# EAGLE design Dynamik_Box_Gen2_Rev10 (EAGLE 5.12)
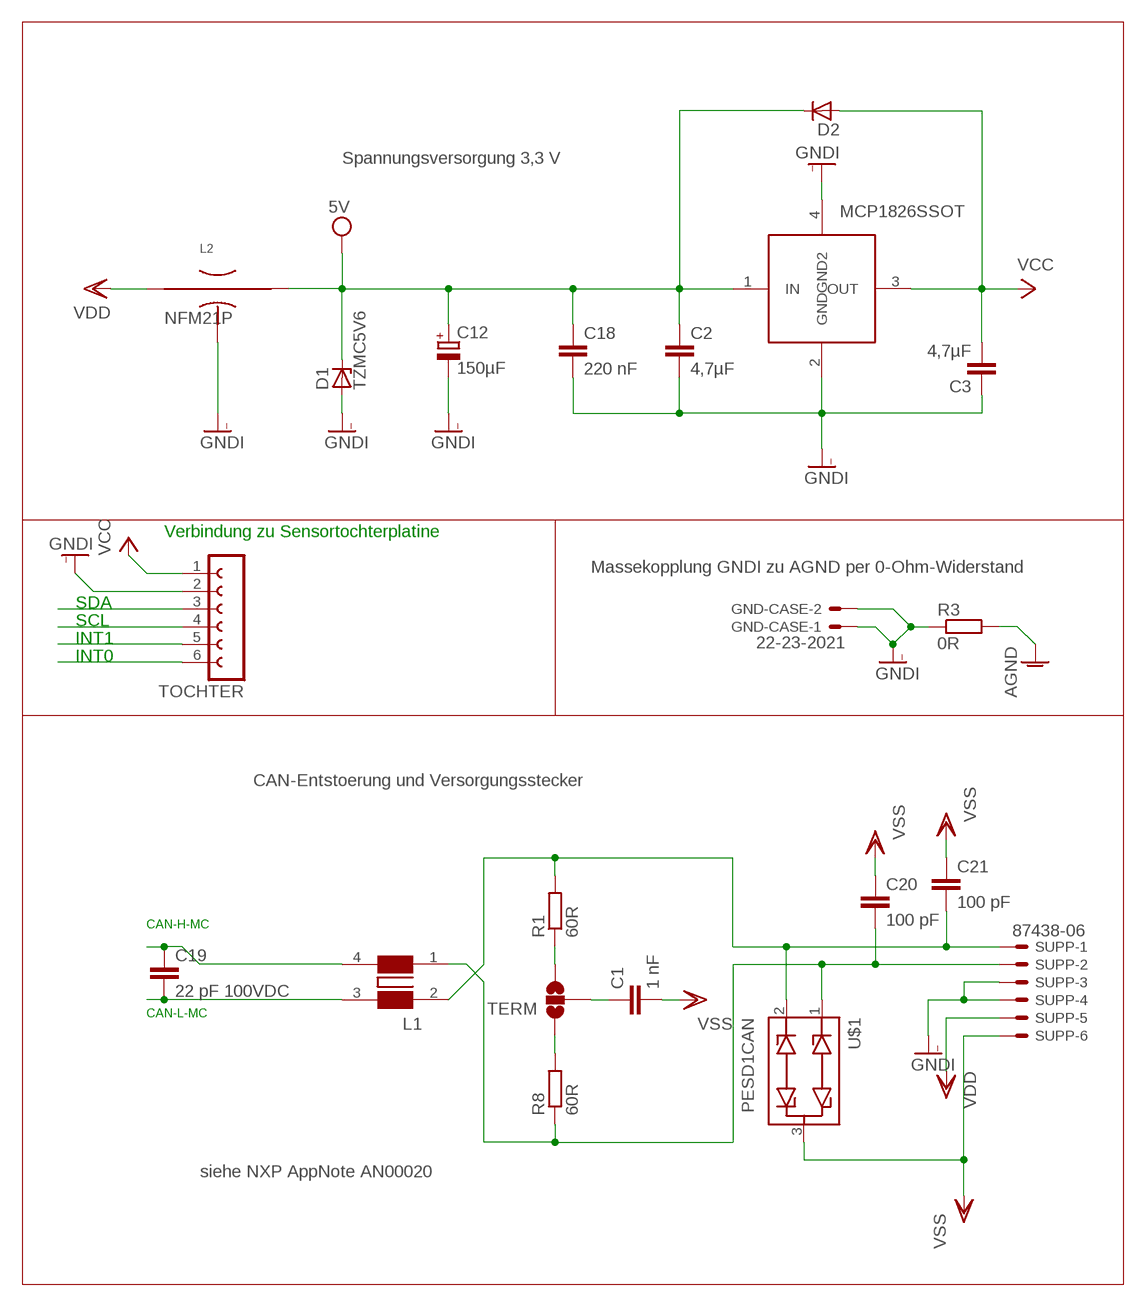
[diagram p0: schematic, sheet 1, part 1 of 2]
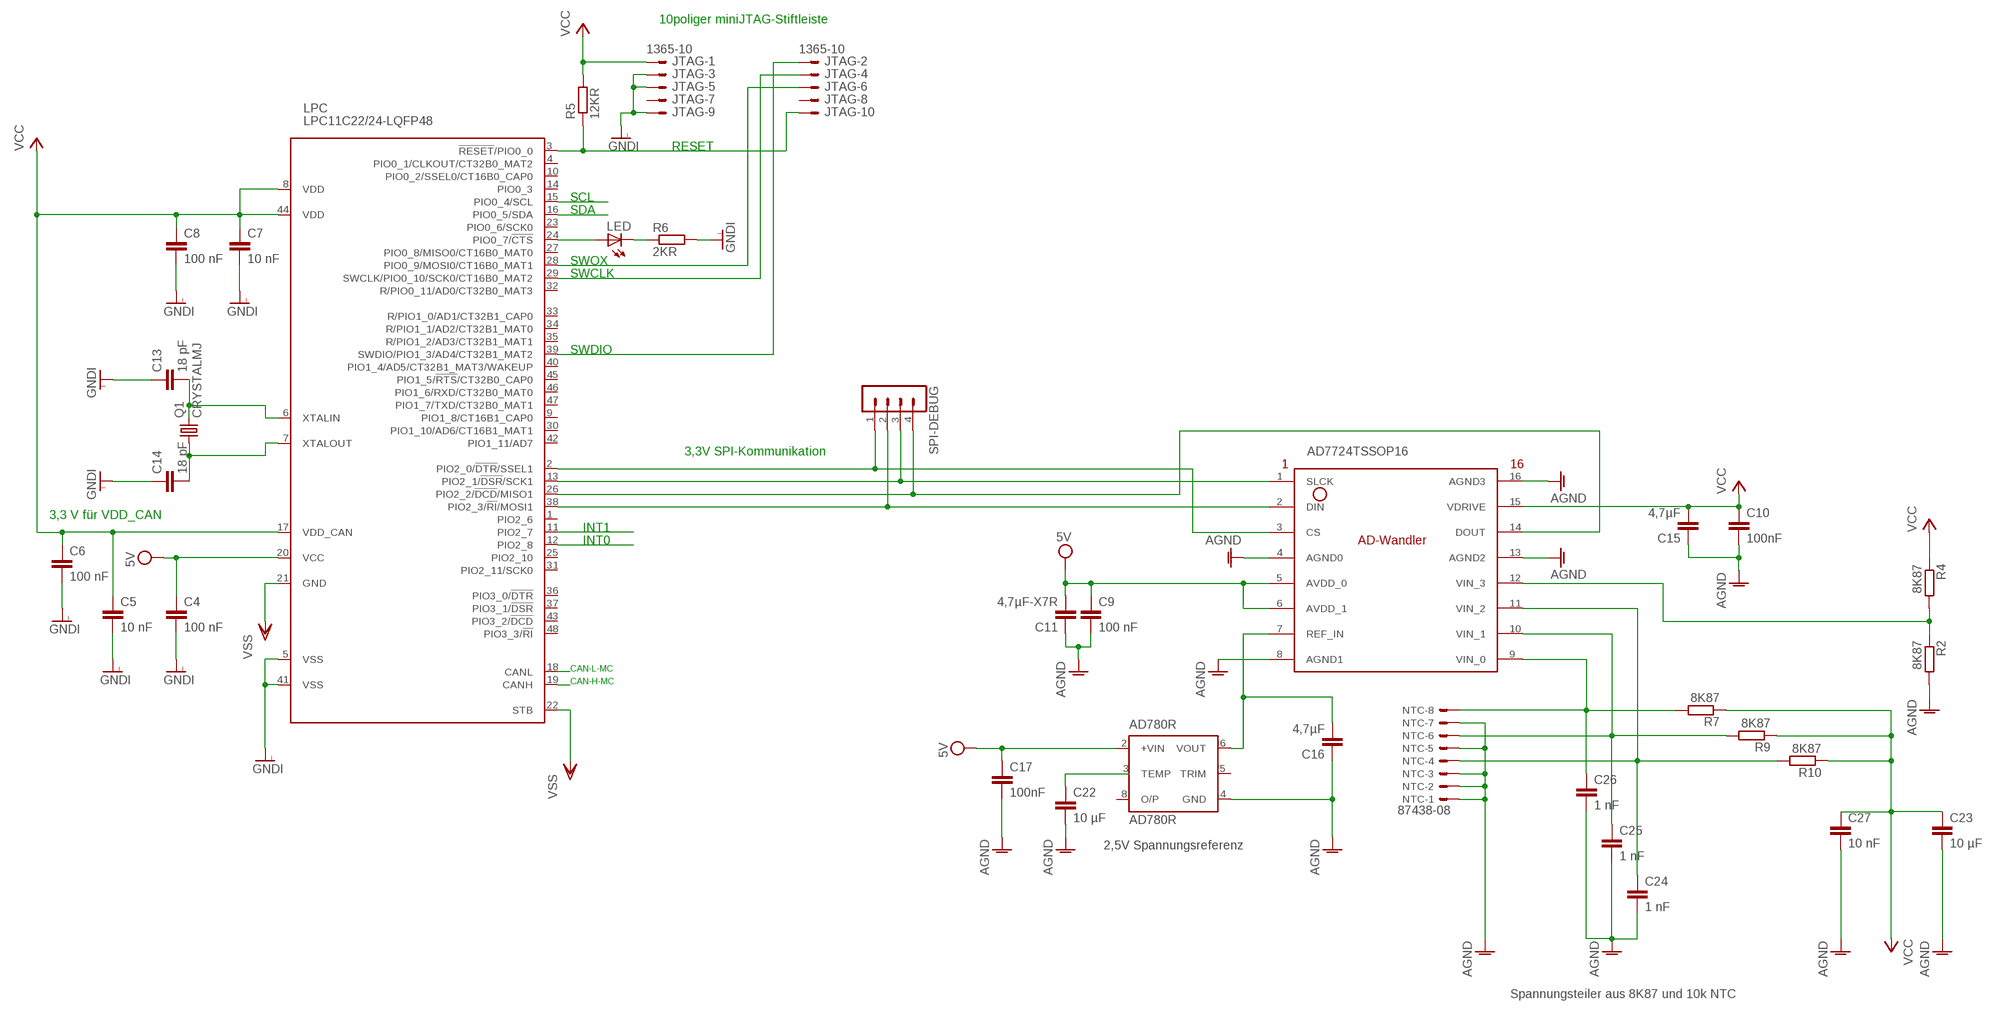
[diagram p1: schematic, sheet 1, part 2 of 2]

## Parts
AD780R  AD780R  [SO8]
AD7724  AD7724TSSOP16  [TSSOP16]
C1  1 nF  C-EUC0603  [C0603]
C2  4,7µF  C-EUC0805  [C0805]
C3  4,7µF  C-EUC0805  [C0805]
C4  100 nF  C-EUC0603  [C0603]
C5  10 nF  C-EUC0603  [C0603]
C6  100 nF  C-EUC0603  [C0603]
C7  10 nF  C-EUC0603  [C0603]
C8  100 nF  C-EUC0603  [C0603]
C9  100 nF  C-EUC0603  [C0603]
C10  100nF  C-EUC0603  [C0603]
C11  4,7µF-X7R  C-EUC0805  [C0805]
C12  150µF  CPOL-EU150CLZ-1014  [150CLZ-1014]
C13  18 pF  C-EUC0603  [C0603]
C14  18 pF  C-EUC0603  [C0603]
C15  4,7µF  C-EUC0805  [C0805]
C16  4,7µF  C-EUC0805  [C0805]
C17  100nF  C-EUC0603  [C0603]
C18  220 nF  C-EUC0805  [C0805]
C19  22 pF 100VDC  C-EUC0603  [C0603]
C20  100 pF  C-EUC1206  [C1206]
C21  100 pF  C-EUC1206  [C1206]
C22  10 µF  C-EUC0603  [C0603]
C23  10 µF  C-EUC0603  [C0603]
C24  1 nF  C-EUC0603  [C0603]
C25  1 nF  C-EUC0603  [C0603]
C26  1 nF  C-EUC0603  [C0603]
C27  10 nF  C-EUC0603  [C0603]
D1  TZMC5V6  [MINIMELF]
D2  D-A1-C3  [SOT23]
GND-CASE  22-23-2021  [22-23-2021]
JTAG  1365-10  [1365-10]
L1  WE-SL2  [WE-SL2_74422...]
L2  NFM21PN  [NFM21P]
LED  LEDSMT1206  [1206]
LPC  LPC11C22/24-LQFP48  [LQFP48]
MCP1826S  MCP1826SSOT  [SOT223]
NTC  87438-08  [87438-08]
Q1  CRYSTALMJ  [MJ]
R1  60R  R-EU_R0603  [R0603]
R2  8K87  R-EU_R0603  [R0603]
R3  0R  R-EU_R1206  [R1206]
R4  8K87  R-EU_R0603  [R0603]
R5  12KR  R-EU_R0603  [R0603]
R6  2KR  R-EU_R0603  [R0603]
R7  8K87  R-EU_R0603  [R0603]
R8  60R  R-EU_R0603  [R0603]
R9  8K87  R-EU_R0603  [R0603]
R10  8K87  R-EU_R0603  [R0603]
SPI-DEBUG  MA04-1  [MA04-1]
SUPP  87438-06  [87438-06]
TERM  SOLDERJUMPER_2WAYT  [SJ_2]
TOCHTER  FE06-1  [FE06]
U$1  PESD1CAN  [SOT23]

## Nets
3,3VOLT: AD7724.15(VDRIVE) C3.2 C5.1 C6.1 C7.1 C8.1 C10.1 C15.2 C23.1 C27.1 D2.1(A) JTAG.1 LPC.8(VDD) LPC.17(VDD_CAN) LPC.44(VDD) MCP1826S.3(OUT) R4.1 R5.2 R7.1 R9.1 R10.1 TOCHTER.1 ; supply symbol labelled VCC
AD-TEMP: AD780R.3(TEMP) C22.1
AGND: AD780R.4(GND) AD7724.4(AGND0) AD7724.8(AGND1) AD7724.13(AGND2) AD7724.16(AGND3) C9.2 C10.2 C11.1 C15.1 C16.1 C17.2 C22.2 C23.2 C24.2 C25.2 C26.2 C27.2 NTC.1 NTC.2 NTC.3 NTC.5 NTC.7 R2.2 R3.2
CAN-GND: C1.2 C20.1 C21.1 LPC.21(GND) LPC.22(STB) SUPP.6 U$1.3 ; supply symbol labelled VSS
CAN-H-MC: C19.1 L1.4 LPC.19(CANH)
CAN-L-MC: C19.2 L1.3 LPC.18(CANL)
CAN_HIGH: C20.2 L1.1 R8.1 SUPP.2 U$1.1
CAN_LOW: C21.2 L1.2 R1.2 SUPP.1 U$1.2
GNDI: C2.2 C3.1 C4.2 C5.2 C6.2 C7.2 C8.2 C12.- C13.1 C14.1 C18.2 D1.A GND-CASE.1 GND-CASE.2 JTAG.3 JTAG.5 JTAG.9 L2.P$3(GND) LPC.5(VSS) LPC.41(VSS) MCP1826S.2(GND) MCP1826S.4(GND2) R3.1 R6.2 SUPP.3 SUPP.4 TOCHTER.2
INT0: LPC.12(PIO2_8) TOCHTER.6
INT1: LPC.11(PIO2_7) TOCHTER.5
LED: LED.A LPC.24(PIO0_7/!CTS!)
LED2: LED.C R6.1
MISO: AD7724.14(DOUT) LPC.26(PIO2_2/!DCD!/MISO1) SPI-DEBUG.4
MOSI: AD7724.2(DIN) LPC.38(PIO2_3/!RI!/MOSI1) SPI-DEBUG.2
RESET: JTAG.10 LPC.3(!RESET!/PIO0_0) R5.1
SCK: AD7724.1(SLCK) LPC.13(PIO2_1/!DSR!/SCK1) SPI-DEBUG.3
SCL: LPC.15(PIO0_4/SCL) TOCHTER.4
SDA: LPC.16(PIO0_5/SDA) TOCHTER.3
SSEL: AD7724.3(CS) LPC.2(PIO2_0/!DTR!/SSEL1) SPI-DEBUG.1
SWCLK: JTAG.4 LPC.29(SWCLK/PIO0_10/SCK0/CT16B0_MAT2)
SWDIO: JTAG.2 LPC.39(SWDIO/PIO1_3/AD4/CT32B1_MAT2)
SWOX: JTAG.6 LPC.28(PIO0_9/MOSI0/CT16B0_MAT1)
TERM1: R8.2 TERM.1
TERM2: R1.1 TERM.3
TERM3: C1.1 TERM.2
V_PREC: AD780R.6(VOUT) AD7724.7(REF_IN) C16.2
VDD: AD780R.2(+VIN) AD7724.5(AVDD_0) AD7724.6(AVDD_1) C2.1 C4.1 C9.1 C11.2 C12.+ C17.1 C18.1 D1.C D2.3(C) L2.P$4(OUT) LPC.20(VCC) MCP1826S.1(IN) ; supply symbol labelled 5V
VDD_UNGEFILTER: L2.P$1(IN) SUPP.5 ; supply symbol labelled VDD
VIN_0: AD7724.9(VIN_0) C26.1 NTC.8 R7.2
VIN_1: AD7724.10(VIN_1) C25.1 NTC.6 R9.2
VIN_2: AD7724.11(VIN_2) C24.1 NTC.4 R10.2
VIN_3: AD7724.12(VIN_3) R2.1 R4.2
XTALIN: C13.2 LPC.6(XTALIN) Q1.P$3
XTALOUT: C14.2 LPC.7(XTALOUT) Q1.P$1
Unconnected: AD780R.5(TRIM) AD780R.8(O/P) JTAG.7 JTAG.8 LPC.1(PIO2_6) LPC.4(PIO0_1/CLKOUT/CT32B0_MAT2) LPC.9(PIO1_8/CT16B1_CAP0) LPC.10(PIO0_2/SSEL0/CT16B0_CAP0) LPC.14(PIO0_3) LPC.23(PIO0_6/SCK0) LPC.25(PIO2_10) LPC.27(PIO0_8/MISO0/CT16B0_MAT0) LPC.30(PIO1_10/AD6/CT16B1_MAT1) LPC.31(PIO2_11/SCK0) LPC.32(R/PIO0_11/AD0/CT32B0_MAT3) LPC.33(R/PIO1_0/AD1/CT32B1_CAP0) LPC.34(R/PIO1_1/AD2/CT32B1_MAT0) LPC.35(R/PIO1_2/AD3/CT32B1_MAT1) LPC.36(PIO3_0/!DTR!) LPC.37(PIO3_1/!DSR!) LPC.40(PIO1_4/AD5/CT32B1_MAT3/WAKEUP) LPC.42(PIO1_11/AD7) LPC.43(PIO3_2/!DCD!) LPC.45(PIO1_5/!RTS!/CT32B0_CAP0) LPC.46(PIO1_6/RXD/CT32B0_MAT0) LPC.47(PIO1_7/TXD/CT32B0_MAT1) LPC.48(PIO3_3/!RI!) Q1.P$2(GND) Q1.P$4(GND1)

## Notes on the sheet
- 10poliger miniJTAG-Stiftleiste
- Spannungsversorgung 3,3 V
- RESET
- SCL
- SDA
- NFM21P
- SWOX
- SWCLK
- SWDIO
- Verbindung zu Sensortochterplatine
- Massekopplung GNDI zu AGND per 0-Ohm-Widerstand
- SDA
- SCL | 3,3V SPI-Kommunikation
- INT1
- INT0
- 3,3 V für VDD_CAN
- INT1
- INT0
- CAN-Entstoerung und Versorgungsstecker
- CAN-H-MC | CAN-L-MC
- CAN-H-MC
- CAN-L-MC
- siehe NXP AppNote AN00020 | 2,5V Spannungsreferenz
- Spannungsteiler aus 8K87 und 10k NTC

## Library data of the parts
AD780R = analog-devices:AD780: High Precision Reference 2.5V/3.0V Source: http://www.analog.com/UploadedFiles/Data_Sheets/AD780.pdf
AD7724 = IRT-lib_Rev06:AD7724: AD7924, AD-Umsetzer mit 4 Kanälen, 12 Bit Auflösung und SPI-Schnittstelle. TSSOP16-Gehäuse.
C1-C11 C13-C27 = resistor:C-EU: CAPACITOR, European symbol
C12 = resistor:CPOL-EU: POLARIZED CAPACITOR, European symbol
D1 = IRT-lib_Rev14:TZMC5V6: Vishay Silicon Epitaxial Planar Z?Diodes
D2 = semicon-smd-ipc:D-: DIODE
GND-CASE = con-molex:22-23-2021: .100" (2.54mm) Center Header - 2 Pin; MF: MOLEX; MPN: 22-23-2021; OC_FARNELL: 1462926; OC_NEWARK: 25C3832
JTAG = con-leotronics:1365-10: DUAL ROW STRAIGHT HEADER 1364 SERIES. 1.27mm x 1.27mm. Without Fixing Post. SMT Source: http://www.leotronics.co.uk/Conexcon/Data%20Sheets/sec.%20A/1364ing.pdf
L1 = wuerth_elektronik_v5:WE-SL2: SMD Common-Mode Choke for signal lines WE-SL2 For distortion-free removal of noise from transmitted electrical signals - Double current-compensated choke -- Current compensated choke for data and signal lines -- Power supply systems -- Filter for measurement signals
L2 = IRT-lib_Rev19:NFM21P: Murata Filter for power lines NFM21P Series
LED = led:LED: LED
LPC = lpc1100v1.1:LPC11C22/24-LQFP48: NXP Semiconductors LPC11Cxx microcontrollers ARM 32-bit Cortex-M0 Microcontroller with MPU CPU clock up to 50MHz 32KByte on-chip Flash ROM with In-System Programming (ISP) and In-Application Programming (IAP) via On-Chip Bootloader 8KByte SRAM Nested Vectored Interrupt Controller 2 SPI controllers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
MCP1826S = IRT-lib_Rev04:MCP1826S: LDO-Spannungswandler von Mikrochip im SOT223-3-Gehäuse. 1A max.
NTC = con-molex:87438-08: Wire-to-Board 1.50mm (.059") Pitch Header - Right Angle, SMT, Shrouded Source: http://www.molex.com/product/micro/87438.html; OC_FARNELL: 1756939; OC_NEWARK: unknown
Q1 = IRT-lib_Rev03:CRYSTAL
R1 R2 R4-R10 = resistor:R-EU_: RESISTOR, European symbol
R3 = rcl:R-EU_: RESISTOR, European symbol
SPI-DEBUG = con-lstb:MA04-1: PIN HEADER; OC_FARNELL: unknown; OC_NEWARK: unknown
SUPP = con-molex:87438-06: Wire-to-Board 1.50mm (.059") Pitch Header - Right Angle, SMT, Shrouded Source: http://www.molex.com/product/micro/87438.html; MPN: 87438-0643; OC_FARNELL: 1756938; OC_NEWARK: 88K3155
TERM = SparkFun:SOLDERJUMPER_2WAY: Solder Jumper 2 way solder jumper
TOCHTER = con-lsta:FE06-1: FEMALE HEADER
U$1 = IRT-lib_Rev16:PESD1CAN: PESD1CAN-Schutzdiode SOT23-Gehäuse mit vier intern Z-Dioden zum Absichern von CAN-Teilnehmern gegen ESD o.ä. Datenblatt NXP PESD1CAN; PESD1CAN: N

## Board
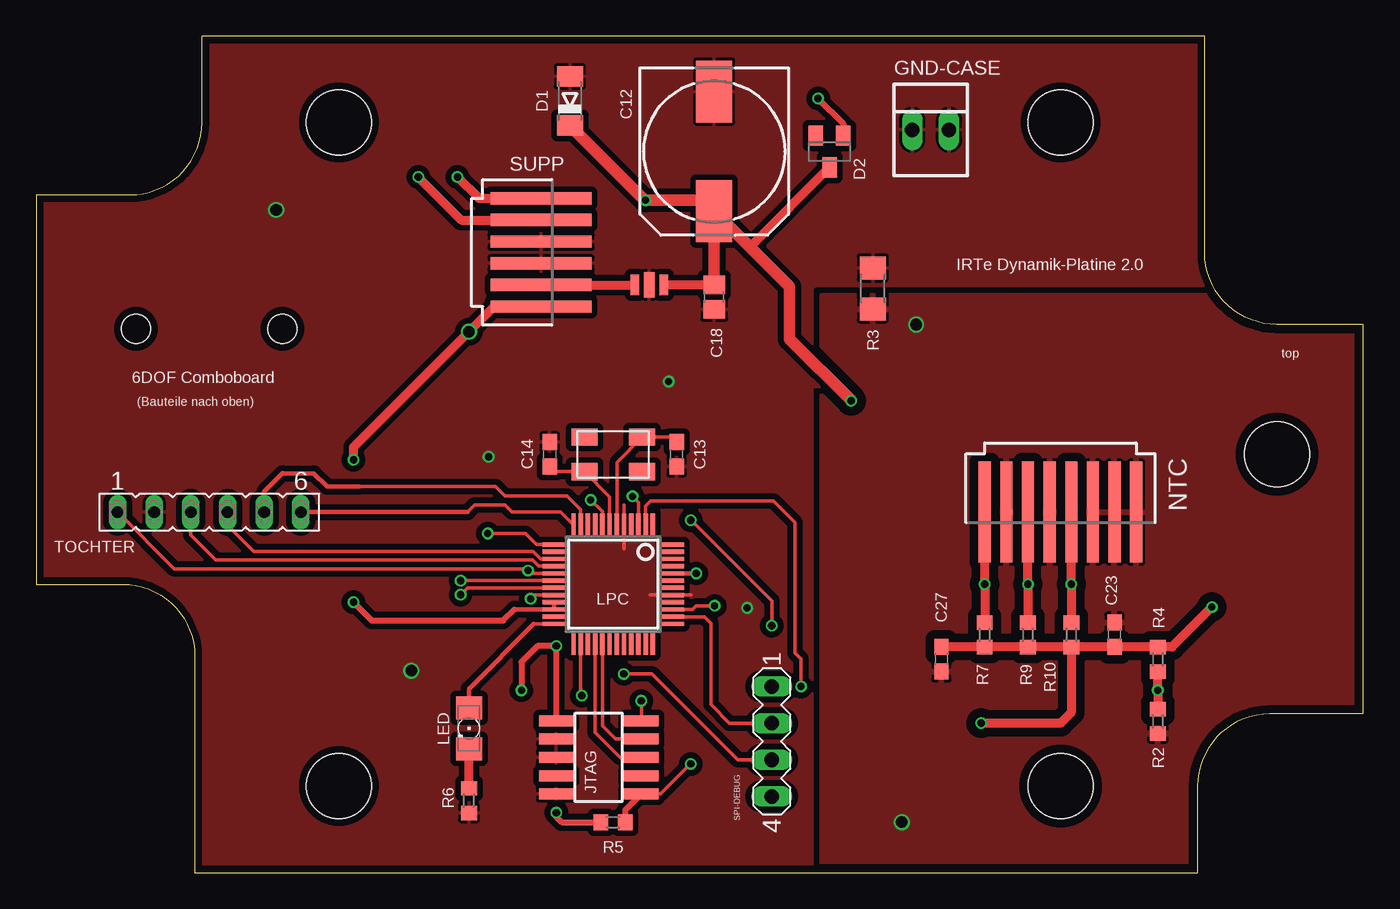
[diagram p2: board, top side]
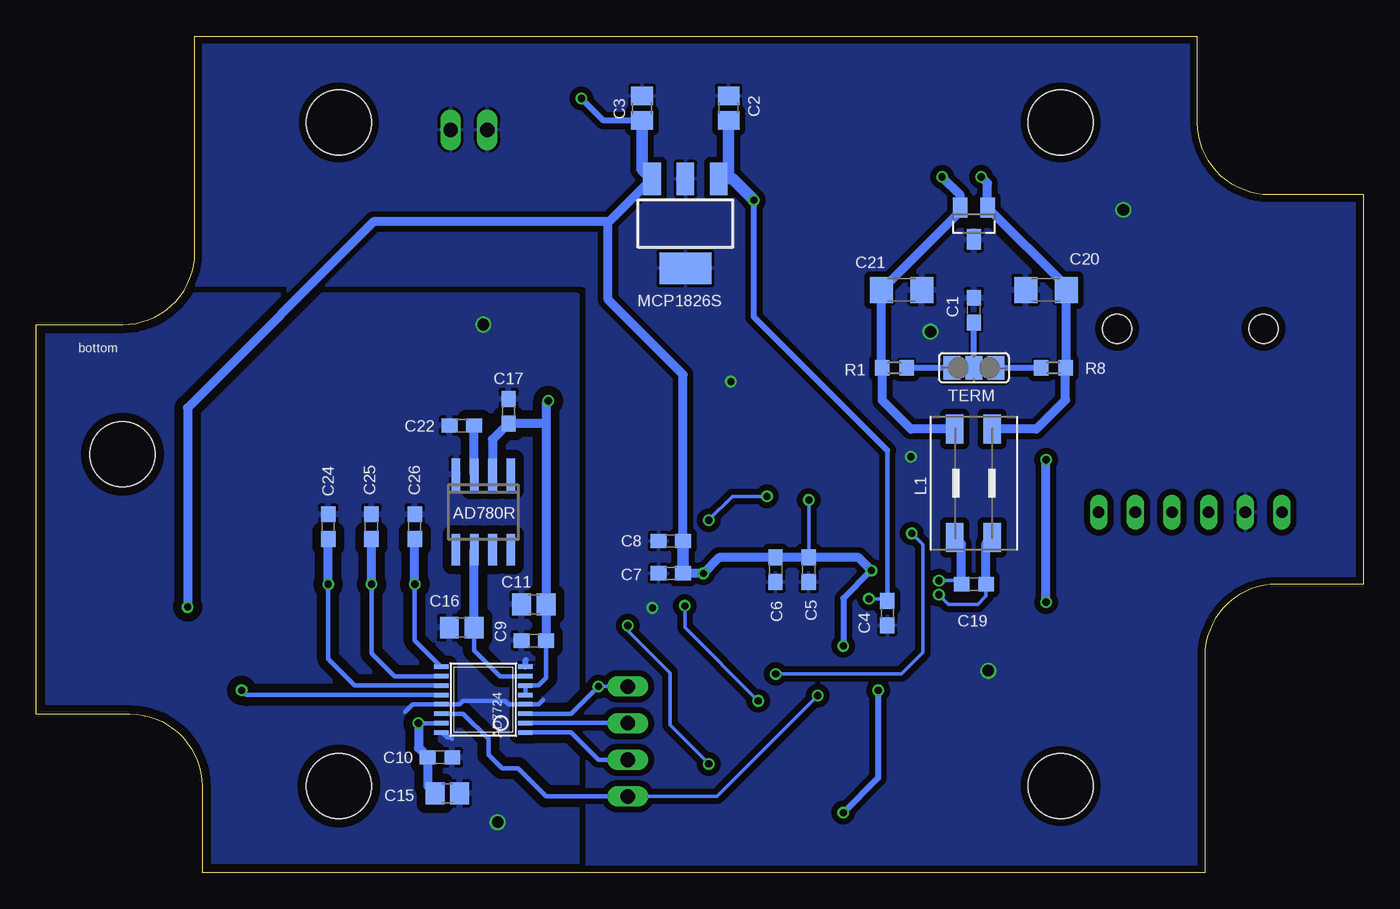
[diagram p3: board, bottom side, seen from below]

Size 92 x 58 mm. Coordinates in mm from the lower left corner, seen from the top.
Outline: 0,47 0,20 6,20 arc-90 11,15 11,0 80.5,0 80.5,6 arc-90 85.5,11 92,11 92,38 86,38 arc-90 81,43 81,58 11.5,58 11.5,52 arc-90 6.5,47 0,47
Copper layers (1*16): Top 0.035mm / dielectric 1.5mm / Bottom 0.035mm
Design rules "leiton *": minimum track width 6mil, minimum drill 0.3mm, track to track 6mil, track to pad 6mil, pad to pad 6mil, via to via 6mil, smd to smd 6mil, copper to edge 20mil, drill to drill 8mil, minimum pad ring 8mil, minimum via ring 6mil, stop-mask expansion 3mil, vias tented up to drill 0mil, thermal gap 8mil
Holes 4.5 mm at 21,6 21,52 71,52 71,6 86,29
Holes 2 mm at 6.92,37.7 17.08,37.7
tKeepout: area 16.5,1.5 to 25.5,10.5; area 66.5,1.5 to 75.5,10.5; area 66.5,47.5 to 75.5,56.5; area 16.5,47.5 to 25.5,56.5
bKeepout: area 16.5,47.5 to 25.5,56.5; area 66.5,47.5 to 75.5,56.5; area 66.5,1.5 to 75.5,10.5; area 16.5,1.5 to 25.5,10.5

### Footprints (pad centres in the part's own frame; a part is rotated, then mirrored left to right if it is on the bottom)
SO8 = smd 0.6 x 2.2: 1 -1.905,-2.6; 2 -0.635,-2.6; 3 0.635,-2.6; 4 1.905,-2.6; 5 1.905,2.6; 6 0.635,2.6; 7 -0.635,2.6; 8 -1.905,2.6
TSSOP16 = smd 0.305 x 0.991: 1 -2.275,-2.918; 2 -1.625,-2.918; 3 -0.975,-2.918; 4 -0.325,-2.918; 5 0.325,-2.918; 6 0.975,-2.918; 7 1.625,-2.918; 8 2.275,-2.918; 9 2.275,2.918; 10 1.625,2.918; 11 0.975,2.918; 12 0.325,2.918; 13 -0.325,2.918; 14 -0.975,2.918; 15 -1.625,2.918; 16 -2.275,2.918
C0603 = smd 1.1 x 1: 1 -0.85,0; 2 0.85,0
C0805 = smd 1.3 x 1.5: 1 -0.85,0; 2 0.85,0
150CLZ-1014 = smd 4.3 x 2.5: + 4.15,0; - -4.15,0
C1206 = smd 1.6 x 1.8: 1 -1.4,0; 2 1.4,0
MINIMELF = smd 1.4 x 1.8: A 1.7,0; C -1.7,0
SOT23 = smd 1 x 1.4: 1 -0.95,-1.1; 2 0.95,-1.1; 3 0,1.1
22-23-2021 = drill 1 long: 1 -1.27,0; 2 1.27,0
1365-10 = smd 0.76 x 2.4: 1 -2.54,-2.95; 2 -2.54,2.95; 3 -1.27,-2.95; 4 -1.27,2.95; 5 0,-2.95; 6 0,2.95; 7 1.27,-2.95; 8 1.27,2.95; 9 2.54,-2.95; 10 2.54,2.95
WE-SL2_74422... = smd 2 x 1.2: 1 -3.75,1.27; 2 -3.75,-1.34; 3 3.75,-1.34; 4 3.75,1.27
NFM21P = smd 0.6 x 1.4: P$1 -1,0; P$4 1,0 | smd 0.7 x 1.75: P$3 0,0
1206 = smd 1.6 x 1.803: A -1.422,0; C 1.422,0
LQFP48 = smd 0.3 x 1.6: 1 -2.75,-4.1; 2 -2.25,-4.1; 3 -1.75,-4.1; 4 -1.25,-4.1; 5 -0.75,-4.1; 6 -0.25,-4.1; 7 0.25,-4.1; 8 0.75,-4.1; 9 1.25,-4.1; 10 1.75,-4.1; 11 2.25,-4.1; 12 2.75,-4.1; 25 2.75,4.1; 26 2.25,4.1; 27 1.75,4.1; 28 1.25,4.1; 29 0.75,4.1; 30 0.25,4.1; 31 -0.25,4.1; 32 -0.75,4.1; 33 -1.25,4.1; 34 -1.75,4.1; 35 -2.25,4.1; 36 -2.75,4.1 | smd 1.6 x 0.3: 13 4.1,-2.75; 14 4.1,-2.25; 15 4.1,-1.75; 16 4.1,-1.25; 17 4.1,-0.75; 18 4.1,-0.25; 19 4.1,0.25; 20 4.1,0.75; 21 4.1,1.25; 22 4.1,1.75; 23 4.1,2.25; 24 4.1,2.75; 37 -4.1,2.75; 38 -4.1,2.25; 39 -4.1,1.75; 40 -4.1,1.25; 41 -4.1,0.75; 42 -4.1,0.25; 43 -4.1,-0.25; 44 -4.1,-0.75; 45 -4.1,-1.25; 46 -4.1,-1.75; 47 -4.1,-2.25; 48 -4.1,-2.75
SOT223 = smd 1.219 x 2.235: 1 -2.311,-3.099; 2 0,-3.099; 3 2.311,-3.099 | smd 3.6 x 2.2: 4 0,3.099
87438-08 = smd 7 x 0.85: 1 0,5.25; 2 0,3.75; 3 0,2.25; 4 0,0.75; 5 0,-0.75; 6 0,-2.25; 7 0,-3.75; 8 0,-5.25
MJ = smd 1.8 x 1.2: P$1 -2,-1.2; P$2 2,-1.2; P$3 2,1.2; P$4 -2,1.2
R0603 = smd 1 x 1.1: 1 -0.85,0; 2 0.85,0
R1206 = smd 1.6 x 1.803: 1 -1.422,0; 2 1.422,0
MA04-1 = drill 1.016 long: 1 -3.81,0; 2 -1.27,0; 3 1.27,0; 4 3.81,0
87438-06 = smd 7 x 0.85: 1 0,3.75; 2 0,2.25; 3 0,0.75; 4 0,-0.75; 5 0,-2.25; 6 0,-3.75
SJ_2 = smd 1.168 x 1.6: 1 -1.524,0; 2 0,0; 3 1.524,0
FE06 = drill 0.813 long: 1 -6.35,0; 2 -3.81,0; 3 -1.27,0; 4 1.27,0; 5 3.81,0; 6 6.35,0

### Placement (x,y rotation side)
AD780R  61,25 180 bottom
AD7724  61,12 90 bottom
C1  27,39 90 bottom
C2  44,53 90 bottom
C3  50,53 270 bottom
C4  33,18 270 bottom
C5  38.45,21 270 bottom
C6  40.75,21 270 bottom
C7  48,20.75 180 bottom
C8  48,23 180 bottom
C9  57.5,16.1 180 bottom
C10  64,8 0 bottom
C11  57.5,18.6 0 bottom
C12  47,50 270 top
C13  44.4,29 90 top
C14  35.6,29 270 top
C15  63.5,5.5 180 bottom
C16  62.5,17 0 bottom
C17  59.25,32 90 bottom
C18  47,39.9 270 top
C19  27,20 180 bottom
C20  22,40.4 0 bottom
C21  32,40.4 180 bottom
C22  62.48,31 180 bottom
C23  74.75,16.5 90 top
C24  71.75,24 90 bottom
C25  68.75,24 90 bottom
C26  65.75,24 90 bottom
C27  62.75,14.8 270 top
D1  37,53.5 90 top
D2  55,50 180 top
GND-CASE  62,51.5 0 top
JTAG  39,8 270 top
L1  27,27 270 bottom
L2  42.5,40.75 0 top
LED  30,10 270 top
LPC  40,20 180 top
MCP1826S  47,45 180 bottom
NTC  71,25 270 top
Q1  40,29 0 top
R1  32.5,35 180 bottom
R2  77.75,10.5 270 top
R3  58,40.5 270 top
R4  77.75,14.8 270 top
R5  40,3.5 180 top
R6  30,5 270 top
R7  65.75,16.5 90 top
R8  21.5,35 180 bottom
R9  68.75,16.5 90 top
R10  71.75,16.5 90 top
SPI-DEBUG  51,9.1 270 top
SUPP  35,43 0 top
TERM  27,35 180 bottom
TOCHTER  12,25 0 top
U$1  27,45 180 bottom

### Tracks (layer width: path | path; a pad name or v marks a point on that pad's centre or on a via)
3,3VOLT  (via drill 0.5)
  Top 0.254: TOCHTER.1 9.58,21.07 33.98,21.07 v34.1,20.95 34.3,20.75 LPC.17 | LPC.8 39.25,25.03 v38.44,25.84
  Top 0.305: v45.75,20.75 LPC.44
  Top 0.406: JTAG.1 v36.05,15.72 34.75,15.72 33.64,14.61 v33.64,12.64 | D2.1 55.95,51.92 v54.2,53.67 | R5.2 36.43,3.5 36.05,3.88 v36.05,4.16
  Top 0.61: v65.5,10.37 70.99,10.37 71.75,11.13 R10.1 | R10.1 R9.1 R7.1 C27.1 | R10.1 C23.1 R4.1 78.73,15.65 v81.5,18.42
  Bottom 0.254: v38.44,25.84 C5.1
  Bottom 0.305: AD7724.15 v65.5,10.37
  Bottom 0.406: v36.05,15.72 36.05,19.02 34.12,20.95 v34.1,20.95 | v54.2,53.67 52.68,52.15 C3.2 | v36.05,4.16 33.64,6.57 v33.64,12.64
  Bottom 0.61: C7.1 v45.75,20.75 44.65,21.85 C6.1 C5.1 35,21.85 v34.1,20.95 | C15.2 64.85,6 C10.1 65.5,8.65 v65.5,10.37 | MCP1826S.3 52.29,45.12 52.35,45.12 | v81.5,18.42 81.5,32.23 68.61,45.12 52.35,45.12 | C8.1 47.15,34.52 52.35,39.72 52.35,45.12
  Bottom 0.813: C7.1 C8.1 | MCP1826S.3 50,48.79 C3.2
AD-TEMP
  Bottom 0.61: AD780R.3 C22.1
AGND  (via drill 0.8)
  Bottom 0.305: 63.97,9.72 AD7724.16 63.87,9.72 63.52,9.38 63.26,9.38 63.15,9.27 | 56.86,11.99 57.17,11.68 AD7724.4 59.26,11.68 59.5,11.92 62.4,11.92 62.65,11.68 AD7724.13 65.91,11.68 66.43,11.15
  Bottom 0.406: AD7724.8 58.08,14.72 58.07,14.73
  other vias: 60,3.5 61,38
  pour Bottom (isolate 0.61): 92,0 54.5,0 54.5,40 92,40 92.08,0.14
  pour Top (isolate 0.61): 92,0 54.5,0 54.5,40 92,40
CAN-GND  (via drill 0.5, 0.8)
  Top 0.305: 33.15,18.25 LPC.22 LPC.21
  Top 0.406: 31.75,39.25 SUPP.6 | 33.15,18.25 32.38,17.48 23.27,17.48 v22,18.75
  Top 0.61: 31.75,39.25 v30,37.5 22,29.5 v22,28.63
  Bottom 0.61: v22,18.75 v22,28.63
  pour Bottom: 26,44.5 21.5,40 21.5,35.5 32.5,35.5 32.5,40 28,44.5
CAN-H-MC  (via drill 0.5)
  Top 0.254: v29.42,19.27 29.9,19.75 LPC.19
  Bottom 0.254: C19.1 26.15,19.18 26.72,18.61 28.76,18.61 v29.42,19.27
  Bottom 0.61: C19.1 26.15,22.83 L1.4
CAN-L-MC  (via drill 0.5)
  Top 0.254: v29.42,20.25 LPC.18
  Bottom 0.254: 28.12,20.27 C19.2 28.1,20.25 v29.42,20.25
  Bottom 0.61: L1.3 27.85,22.76 C19.2
CAN_HIGH  (via drill 0.5)
  Top 0.61: SUPP.2 29.47,45.25 v26.49,48.23
  Bottom 0.61: L1.1 22.67,30.75 20.65,32.77 R8.1 20.6,35.05 C20.2 20.6,40.65 U$1.1 26.05,47.79 v26.49,48.23
CAN_LOW  (via drill 0.5)
  Top 0.61: SUPP.1 30.69,46.75 v29.21,48.23
  Bottom 0.61: L1.2 31.35,30.75 33.35,32.75 R1.2 33.4,35.05 C21.2 27.95,45.85 U$1.2 27.95,46.97 v29.21,48.23
GNDI  (via drill 0.5, 0.8)
  Top 0.254: 45.38,19.26 45.37,19.25 LPC.41 42.57,19.25 | 40.74,22.44 40.75,22.45 LPC.5 40.75,25.5 40.76,25.51
  other vias: 16.64,45.95 26,14 49.28,18.36 43.84,34.05 31.36,28.83
  pour Top (isolate 0.406, rank 2): 0,0 92,0 92,58 0,58
  pour Bottom (isolate 0.406, rank 2): 0,0 92,0 92,58 0,58
INT0
  Top 0.254: LPC.12 36.35,25 33,25 32.5,25.5 30.41,25.5 29.91,25
  Top 0.305: TOCHTER.6 29.91,25
INT1
  Top 0.254: LPC.11 37.75,25.18 36.8,26.13 32.49,26.13 31.85,26.77 22.42,26.77
  Top 0.305: TOCHTER.5 15.81,26.42 17.09,27.7 17.1,27.68 19.25,27.68 20.16,26.77 22.42,26.77
LED
  Top 0.254: 34.49,17.25 LPC.24
  Top 0.305: 34.49,17.25 30,12.76 LED.A
LED2
  Top 0.61: R6.1 LED.C
MISO  (via drill 0.5)
  Top 0.254: LPC.26 37.75,12.35 v37.82,12.28
  Bottom 0.254: v37.82,12.28 44.81,5.29 SPI-DEBUG.4
  Bottom 0.305: AD7724.14 62.4,11.03 60.64,9.27 60.64,8.17 59.71,7.24 58.61,7.24 56.66,5.29 SPI-DEBUG.4
MOSI
  Top 0.254: LPC.38 46.33,17.75 46.78,17.3 46.78,11.66 48.07,10.37 SPI-DEBUG.2
  Bottom 0.305: AD7724.2 SPI-DEBUG.2
RESET  (via drill 0.5)
  Top 0.254: JTAG.10 43.29,5.46 v45.37,7.54 | v41.34,26.09 41.75,25.68 LPC.3 | v50.99,17.13 50.99,18.83 v45.38,24.44
  Top 0.406: R5.1 40.85,4.36 JTAG.10
  Bottom 0.254: v45.38,24.44 43.73,26.09 v41.34,26.09 | v45.37,7.54 48.07,10.24 48.07,13.87 50.99,16.79 v50.99,17.13
SCK  (via drill 0.5)
  Top 0.254: SPI-DEBUG.3 48.64,7.83 42.69,13.78 v40.74,13.78 | v31.3,23.52 33.92,23.52 34.69,22.75 LPC.13
  Bottom 0.254: v40.74,13.78 32.02,13.78 30.53,15.27 30.53,22.75 v31.3,23.52
  Bottom 0.305: AD7724.1 54.91,9.72 53.02,7.83 SPI-DEBUG.3
SCL
  Top 0.254: LPC.15 34.97,21.75 34.45,22.27 15.07,22.27 13.27,24.07 TOCHTER.4
SDA
  Top 0.254: LPC.16 34.83,21.25 34.4,21.68 12.46,21.68 10.73,23.41 TOCHTER.3
SSEL  (via drill 0.5)
  Top 0.254: LPC.2 42.25,25.43 42.6,25.78 51.1,25.78 52.6,24.28 52.6,15.23 53.02,14.81 v53.02,12.91
  Bottom 0.254: SPI-DEBUG.1 v53.02,12.91
  Bottom 0.305: AD7724.3 54.91,11.03 v53.02,12.91
SWCLK
  Top 0.254: LPC.29 39.25,10.17 40.15,9.27 JTAG.4
SWDIO  (via drill 0.5)
  Top 0.254: JTAG.2 v41.95,11.91 | v47.03,18.5 45.74,18.5 45.49,18.25 LPC.39
  Bottom 0.254: v47.03,18.5 47.03,16.99 v41.95,11.91
SWOX
  Top 0.254: LPC.28 38.75,9.73 40.48,8 JTAG.6
TERM1
  Bottom 0.406: R8.2 TERM.1
TERM2
  Bottom 0.406: TERM.3 R1.1
TERM3
  Bottom 0.406: TERM.2 C1.1
V_PREC
  Bottom 0.305: AD7724.7 59.85,13.62 61.65,15.42 C16.2
  Bottom 0.61: C16.2 61.63,17.02 AD780R.6
VDD  (via drill 0.5)
  Top 0.254: LPC.20 34.53,19.25 v34.27,18.99
  Top 0.61: C18.1 L2.P$4 | D2.3 49.61,43.51 49.61,43.24
  Top 0.813: v42.25,46.62 46.23,46.62 C12.+ | v56.5,32.72 52.22,37 52.22,40.63 49.61,43.24 C12.+ | v42.25,46.62 43.94,46.62 | D1.C 42.18,46.62 v42.25,46.62 | C12.+ C18.1
  Bottom 0.254: v34.27,18.99 33.14,18.99 C4.1
  Bottom 0.305: AD7724.5 AD7724.6 57.16,12.97 56.65,13.49 C9.1 | C4.1 33,29.27
  Bottom 0.406: 33,29.27 42.25,38.52 v42.25,46.62
  Bottom 0.61: C9.1 C11.2 56.65,31.18 | v56.5,32.72 56.65,32.57 56.65,31.18 | AD780R.2 60.37,30.04 C17.1 56.68,31.15 56.65,31.18
  Bottom 0.813: 44.19,48.1 43.73,48.1 v42.25,46.62 | 44.19,48.1 MCP1826S.1 | C2.1 44,48.29 44.19,48.1
VDD_UNGEFILTER
  Top 0.61: SUPP.5 L2.P$1
VIN_0  (via drill 0.5)
  Top 0.61: R7.2 v65.75,20 NTC.8
  Bottom 0.305: AD7724.9 65.75,16.11 v65.75,20
  Bottom 0.61: v65.75,20 C26.1
VIN_1  (via drill 0.5)
  Top 0.61: NTC.6 v68.75,20 R9.2
  Bottom 0.305: AD7724.10 67.16,13.62 68.75,15.22 v68.75,20
  Bottom 0.61: v68.75,20 C25.1
VIN_2  (via drill 0.5)
  Top 0.61: NTC.4 v71.75,20 R10.2
  Bottom 0.305: AD7724.11 69.92,12.97 71.75,14.81 v71.75,20
  Bottom 0.61: v71.75,20 C24.1
VIN_3  (via drill 0.5)
  Top 0.305: R4.2
  Top 0.61: R2.1 v77.75,12.65 R4.2
  Bottom 0.305: AD7724.12 77.42,12.32 v77.75,12.65
XTALIN
  Top 0.254: LPC.6 40.25,28.45 Q1.P$3 44.05,30.2 C13.2
XTALOUT
  Top 0.254: LPC.7 39.75,26.05 Q1.P$1 35.95,27.8 C14.2

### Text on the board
tNames: IRTe Dynamik-Platine 2.0 | top | 6DOF Comboboard | (Bauteile nach oben)
bNames: bottom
